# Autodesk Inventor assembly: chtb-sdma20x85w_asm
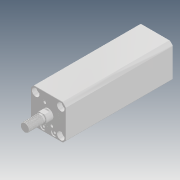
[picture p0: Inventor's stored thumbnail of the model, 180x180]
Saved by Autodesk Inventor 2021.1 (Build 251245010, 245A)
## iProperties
Company: Microsoft
Created: 2018-05
Part Number: chtb-sdma20x85w_asm
Description: STEP AP214
Document SubType Name: Assembly
Designer: user
Title: chtb-sdma20x85w_asm.STEP
Author: Windows
Revision Number: ÈÎºÎ
Sending System: SolidWorks 2015
Preprocessor: SwSTEP 2.0
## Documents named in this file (4)
- D:\Vault_2016\Projekty\Clamptek\Hydraulic\CHTB\CHTB-20\Inventor\CHTB-SDMA20x85W\chtb-sdma20x85w_asm.iam
- D:\Vault_2016\Projekty\Clamptek\Hydraulic\CHTB\CHTB-20\Inventor\CHTB-SDMA20x85W\CHTB-SDMA20X85NBT.ipt
- D:\Vault_2016\Projekty\Clamptek\Hydraulic\CHTB\CHTB-20\Inventor\CHTB-SDMA20x85W\CHTB-SDMA20X85WHSG.ipt
- D:\Vault_2016\Projekty\Clamptek\Hydraulic\CHTB\CHTB-20\Inventor\CHTB-SDMA20x85W\QG_3.ipt
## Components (3 placed, 3 different names)
1. CHTB-SDMA20X85NBT_1
2. CHTB-SDMA20X85WHSG_2
3. QG_3_3
